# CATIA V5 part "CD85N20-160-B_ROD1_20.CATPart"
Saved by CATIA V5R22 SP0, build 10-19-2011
Part number: CD85N20-160-B_ROD1_20
Revision: ANY
Definition: UNKNOWN
Nomenclature: CD85N20-160-B_ROD1_20
Source: Unknown
Bounding box of the stored display mesh (mm): x -10 to 10, y -9.989 to 9.989, z 160.959 to 398.459
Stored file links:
  D:\PER\CAO_PER_MODIF_2025\CAO_PER_pick&place_2024P\Sous_Ensemble_Boite\Verin\CD85N20-160-B_ROD1_20.CATPart
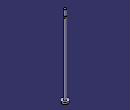
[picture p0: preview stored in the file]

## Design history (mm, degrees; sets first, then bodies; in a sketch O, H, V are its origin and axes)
Body1 "MALE_FLATS" (main body)
  Solid1: solid without history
